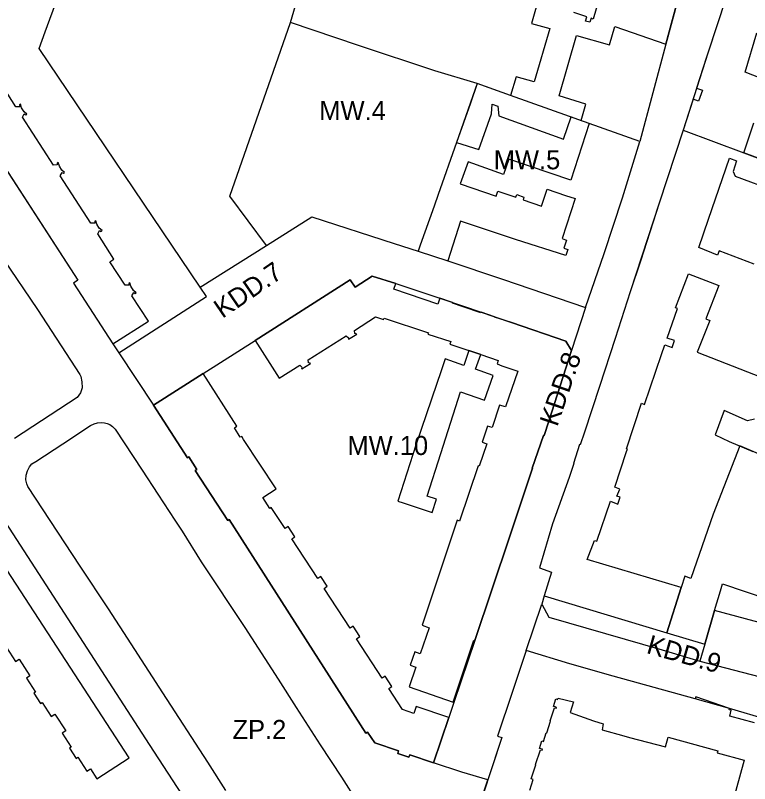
# Model space of a CAD drawing. Extents: x 7424052 to 7425705, y 5546602 to 5547569.
# Drawn here: x 7424972 to 7425164.6, y 5547200.9 to 5547402.5 of the extents above; entities that cross this region are included whole.
import ezdxf

# ---------------------------------------------------------------- set-up
doc = ezdxf.new("R2010")
doc.units = 0
for name, color, linetype in [('linie rozgraniczające', 7, 'Continuous'), ('nieprzekraczalne linie zabudowy', 7, 'Continuous'), ('obowiazujace linie zabudowy', 7, 'Continuous'), ('przeznaczenia terenów', 7, 'Continuous')]:
    doc.layers.add(name, color=color, linetype=linetype)

msp = doc.modelspace()

# ---------------------------------------------------------------- linework, layer by layer
at = {"layer": 'linie rozgraniczające'}
for p, q in [((7424979.78, 5547398.16), (7424986.52, 5547416.78)), ((7425044.17, 5547400.66), (7425048.43, 5547415.4)), ((7425160.51, 5547413.68), (7425153.59, 5547392.63)), ((7425146.34, 5547408.9), (7425142.58, 5547394.99)), ((7425028.21, 5547355.08), (7425044.17, 5547400.66)), ((7425061.96, 5547394.62), (7425044.17, 5547400.66)), ((7424978.19, 5547393.79), (7424979.78, 5547398.16)), ((7425020.45, 5547331.17), (7424978.19, 5547393.79)), ((7425081.99, 5547387.97), (7425061.96, 5547394.62)), ((7425142.58, 5547394.99), (7425135.79, 5547369.42)), ((7425153.59, 5547392.63), (7425147.16, 5547372.35)), ((7425093.12, 5547384.64), (7425081.99, 5547387.97)), ((7425093.12, 5547384.64), (7425087.68, 5547369.12)), ((7425101.87, 5547381.49), (7425093.12, 5547384.64)), ((7425122.45, 5547374.17), (7425101.87, 5547381.49)), ((7424958.41, 5547379.14), (7424988.31, 5547333.01)), ((7425135.79, 5547369.42), (7425122.45, 5547374.17)), ((7425147.16, 5547372.35), (7425140.87, 5547353.27)), ((7425147.16, 5547372.35), (7425163.09, 5547366.42)), ((7425087.68, 5547369.12), (7425082.9, 5547355.52)), ((7425131.26, 5547354.67), (7425135.79, 5547369.42)), ((7425163.09, 5547366.42), (7425169.9, 5547363.89)), ((7425037.82, 5547342.16), (7425028.21, 5547355.08)), ((7425082.9, 5547355.52), (7425081.79, 5547352.43)), ((7425126.4, 5547340.07), (7425131.26, 5547354.67)), ((7425140.87, 5547353.27), (7425133.21, 5547329.93)), ((7425081.79, 5547352.43), (7425078.18, 5547342.21)), ((7425037.82, 5547342.16), (7425049.73, 5547349.69)), ((7425049.73, 5547349.69), (7425071.29, 5547342.69)), ((7425071.29, 5547342.69), (7425077.63, 5547340.63)), ((7425020.45, 5547331.17), (7425037.82, 5547342.16)), ((7425078.18, 5547342.21), (7425077.63, 5547340.63)), ((7425077.63, 5547340.63), (7425085.42, 5547338.09)), ((7425121.54, 5547325.82), (7425126.4, 5547340.07)), ((7424968.75, 5547338.59), (7424977.79, 5547325.37)), ((7425085.42, 5547338.09), (7425099.76, 5547333.31)), ((7424988.31, 5547333.01), (7424987.19, 5547332.23)), ((7425034.89, 5547317.19), (7425059.82, 5547333.16)), ((7425059.82, 5547333.16), (7425061.1, 5547331.18)), ((7425061.1, 5547331.18), (7425065.58, 5547334.1)), ((7425065.58, 5547334.1), (7425071.73, 5547332.17)), ((7425099.76, 5547333.31), (7425121.54, 5547325.82)), ((7424987.19, 5547332.23), (7424997.54, 5547316.35)), ((7425022.12, 5547328.77), (7425020.45, 5547331.17)), ((7425071.73, 5547332.17), (7425083.29, 5547328.28)), ((7424999.07, 5547313.97), (7425022.12, 5547328.77)), ((7425133.21, 5547329.93), (7425129.31, 5547317.69)), ((7425083.29, 5547328.28), (7425089.47, 5547326.17)), ((7424977.79, 5547325.37), (7424988.84, 5547308.24)), ((7425089.47, 5547326.17), (7425102.08, 5547321.92)), ((7425121.54, 5547325.82), (7425117.82, 5547314.6)), ((7425102.08, 5547321.92), (7425116.35, 5547317.03)), ((7425021.23, 5547308.56), (7425034.89, 5547317.19)), ((7425116.35, 5547317.03), (7425117.82, 5547314.6)), ((7425129.31, 5547317.69), (7425125.2, 5547305.13)), ((7424997.54, 5547316.35), (7424999.07, 5547313.97)), ((7425117.82, 5547314.6), (7425111.89, 5547296.03)), ((7424999.07, 5547313.97), (7425008.17, 5547300.22)), ((7425008.17, 5547300.22), (7425021.23, 5547308.56)), ((7424988.84, 5547308.24), (7424989.16, 5547307.73)), ((7424989.16, 5547307.73), (7424989.43, 5547306.38)), ((7424989.43, 5547306.38), (7424989.45, 5547304.76)), ((7424989.45, 5547304.76), (7424989.07, 5547303.47)), ((7425125.2, 5547305.13), (7425121.27, 5547293.17)), ((7424989.07, 5547303.47), (7424988.18, 5547302.22)), ((7424988.18, 5547302.22), (7424971.75, 5547291.5)), ((7425017.07, 5547286.41), (7425008.18, 5547300.23)), ((7424984.37, 5547290.09), (7424991.66, 5547294.88)), ((7424991.66, 5547294.88), (7424992.63, 5547295.38)), ((7424992.63, 5547295.38), (7424993.5, 5547295.63)), ((7424993.5, 5547295.63), (7424994.46, 5547295.72)), ((7424994.46, 5547295.72), (7424995.31, 5547295.64)), ((7424995.31, 5547295.64), (7424996.05, 5547295.45)), ((7424996.05, 5547295.45), (7424996.74, 5547295.14)), ((7424996.74, 5547295.14), (7424997.44, 5547294.66)), ((7424997.44, 5547294.66), (7424998.15, 5547293.93)), ((7425111.89, 5547296.03), (7425110.63, 5547292.24)), ((7424998.15, 5547293.93), (7425005.2, 5547283.18)), ((7425110.49, 5547292.29), (7425107.51, 5547283.73)), ((7425110.63, 5547292.24), (7425110.49, 5547292.29)), ((7425121.27, 5547293.17), (7425120.14, 5547289.84)), ((7424977.35, 5547285.45), (7424984.37, 5547290.09)), ((7425119.96, 5547289.88), (7425118.33, 5547284.94)), ((7425120.14, 5547289.84), (7425119.96, 5547289.88)), ((7425017.46, 5547286.65), (7425017.07, 5547286.41)), ((7425019.58, 5547283.36), (7425017.46, 5547286.65)), ((7424975.67, 5547284.05), (7424976.29, 5547284.82)), ((7424976.29, 5547284.82), (7424977.35, 5547285.45)), ((7425118.47, 5547284.89), (7425117.21, 5547281.22)), ((7425118.33, 5547284.94), (7425118.47, 5547284.89)), ((7424974.79, 5547281.88), (7424975.12, 5547283.03)), ((7424975.12, 5547283.03), (7424975.67, 5547284.05)), ((7425005.2, 5547283.18), (7425009.29, 5547276.93)), ((7425019.11, 5547283.06), (7425019.58, 5547283.36)), ((7425027.65, 5547269.94), (7425019.11, 5547283.06)), ((7425107.65, 5547283.68), (7425106.39, 5547280)), ((7425107.51, 5547283.73), (7425107.65, 5547283.68)), ((7424974.73, 5547280.67), (7424974.79, 5547281.88)), ((7424974.93, 5547279.63), (7424974.73, 5547280.67)), ((7425117.21, 5547281.22), (7425112.87, 5547269.13)), ((7424975.23, 5547278.87), (7424974.93, 5547279.63)), ((7424988.97, 5547258.01), (7424975.23, 5547278.87)), ((7425106.39, 5547280), (7425101.54, 5547265.63)), ((7425009.29, 5547276.93), (7425013.79, 5547270.03)), ((7424967.35, 5547272.4), (7425007.07, 5547211.22)), ((7425028.07, 5547270.21), (7425027.65, 5547269.94)), ((7425063.86, 5547214.15), (7425028.07, 5547270.21)), ((7425013.79, 5547270.03), (7425015.67, 5547267.16)), ((7425112.87, 5547269.13), (7425109.47, 5547257.58)), ((7425015.67, 5547267.16), (7425020.67, 5547259.12)), ((7425101.54, 5547265.63), (7425092.51, 5547238.49)), ((7424996.35, 5547246.79), (7424988.97, 5547258.01)), ((7425020.67, 5547259.12), (7425032.15, 5547241.92)), ((7425109.47, 5547257.58), (7425112.6, 5547256.42)), ((7425112.6, 5547256.42), (7425110.71, 5547250.22)), ((7425110.71, 5547250.22), (7425110.1, 5547248.06)), ((7425105.98, 5547235.9), (7425110.1, 5547248.06)), ((7425110.1, 5547248.06), (7425111.93, 5547244.59)), ((7425002.31, 5547237.66), (7424996.35, 5547246.79)), ((7425111.93, 5547244.59), (7425141.61, 5547236.01)), ((7425032.15, 5547241.92), (7425040.87, 5547228.33)), ((7425092.51, 5547238.49), (7425087.01, 5547222.24)), ((7425010.64, 5547224.75), (7425002.31, 5547237.66)), ((7425105.98, 5547235.9), (7425102.28, 5547224.84)), ((7425117.37, 5547232.36), (7425105.98, 5547235.9)), ((7425141.61, 5547236.01), (7425151.52, 5547233.04)), ((7425128.76, 5547229.1), (7425117.37, 5547232.36)), ((7425151.52, 5547233.04), (7425171.67, 5547227.81)), ((7425040.87, 5547228.33), (7425045.63, 5547220.94)), ((7425146.16, 5547224.31), (7425128.76, 5547229.1)), ((7425022.42, 5547206.57), (7425010.64, 5547224.75)), ((7425102.28, 5547224.84), (7425098.44, 5547213.42)), ((7425150.26, 5547223.17), (7425146.16, 5547224.31)), ((7425087.01, 5547222.24), (7425085.66, 5547218.27)), ((7425150.42, 5547223.71), (7425150.26, 5547223.17)), ((7425159.3, 5547220.65), (7425150.42, 5547223.71)), ((7425045.63, 5547220.94), (7425051.91, 5547211.11)), ((7425169.36, 5547217.69), (7425159.3, 5547220.65)), ((7425085.66, 5547218.27), (7425081.67, 5547206.43)), ((7425064.29, 5547214.41), (7425063.86, 5547214.15)), ((7425066.24, 5547211.66), (7425064.29, 5547214.41)), ((7425072.48, 5547209.54), (7425066.24, 5547211.66)), ((7425099.58, 5547213.04), (7425095.9, 5547201.94)), ((7425098.44, 5547213.42), (7425099.58, 5547213.04)), ((7425007.07, 5547211.22), (7425021.71, 5547188.75)), ((7425051.91, 5547211.11), (7425057.52, 5547202.6)), ((7425072.25, 5547208.86), (7425072.48, 5547209.54)), ((7425075.19, 5547207.88), (7425072.25, 5547208.86)), ((7425075.42, 5547208.54), (7425075.19, 5547207.88)), ((7425081.67, 5547206.43), (7425075.42, 5547208.54)), ((7425027.13, 5547199.15), (7425022.42, 5547206.57)), ((7425089.09, 5547203.92), (7425081.67, 5547206.43)), ((7425095.9, 5547201.94), (7425089.09, 5547203.92)), ((7425057.52, 5547202.6), (7425064.98, 5547191.05)), ((7425089.21, 5547181.77), (7425095.9, 5547201.94))]:
    msp.add_line(p, q, dxfattribs=at)
at = {"layer": 'nieprzekraczalne linie zabudowy'}
for p, q in [((7425037.82, 5547342.16), (7425049.73, 5547349.69)), ((7425049.73, 5547349.69), (7425071.29, 5547342.69)), ((7425071.29, 5547342.69), (7425077.63, 5547340.63)), ((7425090.91, 5547314.54), (7425089.61, 5547310.68)), ((7425094.06, 5547313.54), (7425090.91, 5547314.54)), ((7425092.69, 5547309.66), (7425094.06, 5547313.54)), ((7425084.69, 5547312.39), (7425083.55, 5547309.01)), ((7425089.61, 5547310.68), (7425084.69, 5547312.39)), ((7425083.55, 5547309.01), (7425082.52, 5547305.9)), ((7425097.27, 5547308.03), (7425092.69, 5547309.66)), ((7425095.03, 5547301.55), (7425097.27, 5547308.03)), ((7425082.52, 5547305.9), (7425076.97, 5547289.72)), ((7425083.55, 5547287.55), (7425088.73, 5547303.74)), ((7425088.73, 5547303.74), (7425095.03, 5547301.55)), ((7425076.97, 5547289.72), (7425072.29, 5547275.03)), ((7425161.98, 5547289.55), (7425155.02, 5547271.65)), ((7425169.76, 5547286.23), (7425161.98, 5547289.55)), ((7425079.96, 5547276.32), (7425083.55, 5547287.55)), ((7425082.39, 5547275.55), (7425079.96, 5547276.32)), ((7425072.29, 5547275.03), (7425073.65, 5547274.59)), ((7425073.65, 5547274.59), (7425081.27, 5547272.11)), ((7425081.27, 5547272.11), (7425082.39, 5547275.55)), ((7425155.02, 5547271.65), (7425149.12, 5547254.77)), ((7425147.57, 5547255.41), (7425146.62, 5547252.39)), ((7425149.12, 5547254.77), (7425147.57, 5547255.41)), ((7425146.62, 5547252.39), (7425142.87, 5547240.51)), ((7425156.93, 5547251.53), (7425157.49, 5547253.4)), ((7425157.49, 5547253.4), (7425169.35, 5547249.33)), ((7425155.33, 5547246.36), (7425156.93, 5547251.53)), ((7425152.8, 5547237.51), (7425155.33, 5547246.36)), ((7425142.87, 5547240.51), (7425152.8, 5547237.51))]:
    msp.add_line(p, q, dxfattribs=at)
at = {"layer": 'obowiazujace linie zabudowy'}
for p, q in [((7425021.23, 5547308.56), (7425008.17, 5547300.22)), ((7425030.08, 5547294.73), (7425021.23, 5547308.56)), ((7425008.17, 5547300.22), (7425017.07, 5547286.41)), ((7425029.43, 5547294.25), (7425030.08, 5547294.73)), ((7425030.91, 5547291.87), (7425029.43, 5547294.25)), ((7425031.39, 5547291.98), (7425030.91, 5547291.87)), ((7425031.84, 5547291.27), (7425031.39, 5547291.98)), ((7425031.78, 5547291.22), (7425031.84, 5547291.27)), ((7425040.41, 5547278.3), (7425031.78, 5547291.22)), ((7425017.07, 5547286.41), (7425017.46, 5547286.65)), ((7425017.46, 5547286.65), (7425019.58, 5547283.36)), ((7425019.58, 5547283.36), (7425019.11, 5547283.06)), ((7425019.11, 5547283.06), (7425027.65, 5547269.94)), ((7425036.91, 5547276.02), (7425040.41, 5547278.3)), ((7425038.75, 5547273.17), (7425036.91, 5547276.02)), ((7425036.91, 5547276.02), (7425036.91, 5547276.02)), ((7425039.09, 5547273.4), (7425038.75, 5547273.17)), ((7425042.7, 5547267.86), (7425039.09, 5547273.4)), ((7425027.65, 5547269.94), (7425028.07, 5547270.21)), ((7425028.07, 5547270.21), (7425063.86, 5547214.15)), ((7425043.53, 5547268.39), (7425042.7, 5547267.86)), ((7425045.28, 5547265.71), (7425043.53, 5547268.39)), ((7425044.48, 5547265.2), (7425045.28, 5547265.71)), ((7425051.28, 5547254.77), (7425044.48, 5547265.2)), ((7425052.09, 5547255.3), (7425051.28, 5547254.77)), ((7425053.77, 5547252.72), (7425052.09, 5547255.3)), ((7425052.94, 5547252.17), (7425053.77, 5547252.72)), ((7425059.75, 5547241.72), (7425052.94, 5547252.17)), ((7425155.33, 5547246.36), (7425152.8, 5547237.51)), ((7425175.68, 5547240.94), (7425155.33, 5547246.36)), ((7425060.55, 5547242.24), (7425059.75, 5547241.72)), ((7425062.31, 5547239.55), (7425060.55, 5547242.24)), ((7425061.45, 5547238.95), (7425062.31, 5547239.55)), ((7425068.19, 5547228.62), (7425061.45, 5547238.95)), ((7425152.8, 5547237.51), (7425151.52, 5547233.04)), ((7425151.52, 5547233.04), (7425171.67, 5547227.81)), ((7425068.96, 5547229.12), (7425068.19, 5547228.62)), ((7425070.71, 5547226.44), (7425068.96, 5547229.12)), ((7425069.91, 5547225.92), (7425070.71, 5547226.44)), ((7425073.52, 5547220.38), (7425069.91, 5547225.92)), ((7425076.48, 5547219.31), (7425073.52, 5547220.38)), ((7425077.11, 5547221.16), (7425076.48, 5547219.31)), ((7425085.66, 5547218.27), (7425077.11, 5547221.16)), ((7425081.67, 5547206.43), (7425085.66, 5547218.27)), ((7425063.86, 5547214.15), (7425064.29, 5547214.41)), ((7425064.29, 5547214.41), (7425066.24, 5547211.66)), ((7425066.24, 5547211.66), (7425072.48, 5547209.54)), ((7425072.48, 5547209.54), (7425072.25, 5547208.86)), ((7425072.25, 5547208.86), (7425075.19, 5547207.88)), ((7425075.19, 5547207.88), (7425075.42, 5547208.54)), ((7425075.42, 5547208.54), (7425081.67, 5547206.43))]:
    msp.add_line(p, q, dxfattribs=at)
for points in [[(7425160.51, 5547413.68), (7425153.59, 5547392.63), (7425153.25, 5547391.56), (7425150.67, 5547383.41), (7425152.21, 5547382.86), (7425151.12, 5547379.99), (7425149.75, 5547380.51), (7425147.16, 5547372.35), (7425140.87, 5547353.27), (7425135.9, 5547338.02), (7425133.21, 5547329.93), (7425129.31, 5547317.69), (7425125.2, 5547305.13), (7425121.27, 5547293.17), (7425120.14, 5547289.84), (7425119.96, 5547289.88), (7425118.33, 5547284.94), (7425118.47, 5547284.89), (7425117.21, 5547281.22), (7425112.87, 5547269.13), (7425109.47, 5547257.58), (7425112.6, 5547256.42), (7425110.71, 5547250.22), (7425142.87, 5547240.51), (7425146.62, 5547252.39), (7425121.93, 5547259.77), (7425123.91, 5547264.77), (7425124.48, 5547264.54), (7425128.06, 5547275.06), (7425130.01, 5547274.29), (7425130.63, 5547276.06), (7425129.76, 5547276.39), (7425130.53, 5547278.21), (7425129.23, 5547278.76), (7425132.29, 5547288.05), (7425132.5, 5547288.66), (7425132.27, 5547288.75), (7425136.21, 5547300.74), (7425136.98, 5547300.43), (7425141.43, 5547313.49), (7425142.31, 5547316.07), (7425144.24, 5547315.41), (7425144.84, 5547317.22), (7425142.97, 5547317.84), (7425145.61, 5547325.63), (7425145.08, 5547325.81), (7425148.56, 5547334.73), (7425156.49, 5547331.64), (7425153.07, 5547322.89), (7425154.15, 5547322.44), (7425150.83, 5547314.18), (7425167.56, 5547307.61)], [(7425117.72, 5547375.85), (7425120.37, 5547374.92), (7425121.61, 5547379.18), (7425114.57, 5547381.39), (7425119.17, 5547397.22), (7425127.78, 5547394.76), (7425129.19, 5547399.59), (7425142.58, 5547394.99), (7425146.34, 5547408.9)], [(7425125.26, 5547407.61), (7425123.52, 5547401.54), (7425122.97, 5547401.73), (7425122.63, 5547400.73), (7425121.54, 5547400.99), (7425121.89, 5547402.1), (7425120.78, 5547402.47), (7425118.47, 5547403.26)], [(7425108.75, 5547405.23), (7425107.33, 5547400.34), (7425112.15, 5547399.02), (7425108.08, 5547385.05), (7425103.29, 5547386.37), (7425101.87, 5547381.49), (7425096.21, 5547383.53), (7425093.12, 5547384.64), (7425091.31, 5547379.48), (7425087.68, 5547369.12), (7425093.52, 5547367.29), (7425096.83, 5547376.63), (7425097, 5547379.23), (7425098.54, 5547378.66), (7425098.78, 5547376.16), (7425115.71, 5547370.03), (7425117.72, 5547375.85)], [(7425167.38, 5547386.04), (7425163.36, 5547387.61), (7425166.42, 5547397.9)], [(7424958.41, 5547379.14), (7424988.31, 5547333.01), (7424987.19, 5547332.23), (7424997.54, 5547316.35), (7425006.88, 5547322.26), (7425002.55, 5547328.93), (7425003.01, 5547329.77), (7425003.42, 5547329.55), (7425003.67, 5547329.74), (7425002.93, 5547330.36), (7425002.24, 5547331.43), (7425001.99, 5547332.36), (7425001.73, 5547332.2), (7425001.77, 5547331.75), (7425000.76, 5547331.68), (7424996.73, 5547337.87), (7424997.83, 5547338.57), (7424993.56, 5547345.2), (7424994.05, 5547346.08), (7424994.46, 5547345.84), (7424994.71, 5547346.03), (7424993.98, 5547346.65), (7424993.3, 5547347.72), (7424993.04, 5547348.64), (7424992.79, 5547348.48), (7424992.81, 5547348.01), (7424991.79, 5547347.95), (7424983.74, 5547360.44), (7424984.22, 5547361.32), (7424984.62, 5547361.11), (7424984.87, 5547361.27), (7424984.14, 5547361.89), (7424983.57, 5547362.98), (7424983.18, 5547363.89), (7424982.94, 5547363.75), (7424982.96, 5547363.28), (7424981.98, 5547363.18), (7424973.85, 5547375.79), (7424974.31, 5547376.64), (7424974.73, 5547376.41), (7424975.01, 5547376.58), (7424974.26, 5547377.21), (7424973.55, 5547378.27), (7424973.31, 5547379.21), (7424973.07, 5547379.05), (7424973.09, 5547378.53), (7424972.11, 5547378.49), (7424967.81, 5547385.17)], [(7425117.67, 5547359.3), (7425101.41, 5547364.82), (7425100.03, 5547360.79), (7425090.7, 5547364.1), (7425088.63, 5547358.29), (7425098.07, 5547355.06), (7425098.53, 5547356.4), (7425103.28, 5547354.77), (7425103.53, 5547355.48), (7425105.37, 5547354.85), (7425105.13, 5547354.14), (7425110, 5547352.48), (7425111.5, 5547356.91), (7425116.31, 5547355.28), (7425118.79, 5547354.44), (7425115.39, 5547343.94), (7425116.23, 5547343.65), (7425116.54, 5547343.54), (7425115.79, 5547341.39), (7425116.91, 5547341.12), (7425116.38, 5547339.53), (7425103.16, 5547343.73), (7425088.72, 5547348.55), (7425085.42, 5547338.09), (7425099.76, 5547333.31), (7425121.54, 5547325.82), (7425126.4, 5547340.07), (7425131.26, 5547354.67), (7425135.79, 5547369.42), (7425122.45, 5547374.17), (7425117.67, 5547359.3)], [(7425169.9, 5547363.89), (7425163.09, 5547366.42), (7425165.65, 5547374.29)], [(7425165.76, 5547337.2), (7425156.6, 5547340.77), (7425156.15, 5547339.63), (7425151.21, 5547341.56), (7425153.75, 5547349.03), (7425159.27, 5547365.02), (7425161.13, 5547364.31), (7425160.21, 5547361.51), (7425160.76, 5547360.35), (7425171.22, 5547356.51)], [(7425094.06, 5547313.54), (7425098.63, 5547311.94), (7425098.32, 5547311.07), (7425099.58, 5547310.6), (7425103.72, 5547309.2), (7425100.49, 5547299.76), (7425098.96, 5547300.26), (7425097.02, 5547294.35), (7425095.79, 5547294.7), (7425094.39, 5547290.51), (7425095.63, 5547290.1), (7425093.62, 5547284.22), (7425093.34, 5547284.31), (7425088.45, 5547269.84), (7425087.84, 5547270.04), (7425078.67, 5547242.51), (7425080.54, 5547241.86), (7425078.15, 5547235), (7425076.75, 5547235.51), (7425075.53, 5547232.04), (7425077.01, 5547231.5), (7425075.29, 5547226.31), (7425086.8, 5547222.31), (7425092.24, 5547238.57), (7425092.51, 5547238.49), (7425101.54, 5547265.63), (7425106.39, 5547280), (7425107.65, 5547283.68), (7425107.51, 5547283.73), (7425110.49, 5547292.29), (7425110.63, 5547292.24), (7425111.89, 5547296.03), (7425117.82, 5547314.6), (7425116.35, 5547317.03), (7425102.08, 5547321.92), (7425097.6, 5547323.36), (7425097.62, 5547323.42), (7425094.14, 5547324.6), (7425094.09, 5547324.5), (7425089.42, 5547326.03), (7425086.59, 5547327.03), (7425086.63, 5547327.14), (7425086.38, 5547327.22), (7425083.29, 5547328.28), (7425082.77, 5547326.76), (7425071.2, 5547330.65), (7425071.73, 5547332.17), (7425065.58, 5547334.1), (7425061.1, 5547331.18), (7425059.82, 5547333.16), (7425034.89, 5547317.19), (7425041.2, 5547307.28), (7425046.58, 5547310.69), (7425047.14, 5547310.2), (7425047, 5547310.03), (7425047.14, 5547309.8), (7425049.34, 5547311.19), (7425049.29, 5547311.26), (7425048.84, 5547311.3), (7425048.77, 5547312.09), (7425058.76, 5547318.44), (7425059.36, 5547317.9), (7425059.35, 5547317.51), (7425061.49, 5547318.89), (7425060.99, 5547319.05), (7425060.91, 5547319.8), (7425066.45, 5547323.41), (7425068.56, 5547322.75), (7425068.67, 5547323.07), (7425080.3, 5547319.19), (7425080.16, 5547318.86), (7425086.2, 5547316.9), (7425085.96, 5547316.2), (7425090.92, 5547314.57), (7425094.06, 5547313.54)], [(7425165.81, 5547296.53), (7425164.05, 5547296.15), (7425157.85, 5547298.81), (7425155.56, 5547292.45), (7425159.24, 5547290.72), (7425163.14, 5547289.06), (7425165.41, 5547288.09)], [(7424969.6, 5547236.67), (7424972.01, 5547232.96), (7424972.93, 5547233.63), (7424975.79, 5547229.22), (7424974.85, 5547228.6), (7424977.24, 5547224.94), (7424976.8, 5547224.65), (7424978.56, 5547221.98), (7424978.99, 5547222.25), (7424981.37, 5547218.59), (7424982.32, 5547219.21), (7424985.16, 5547214.79), (7424984.25, 5547214.18), (7424986.63, 5547210.53), (7424986.2, 5547210.24), (7424987.93, 5547207.55), (7424988.38, 5547207.85), (7424990.74, 5547204.22), (7424991.64, 5547204.82), (7424993.33, 5547202.24), (7425001.78, 5547207.7), (7424963.81, 5547266.06)], [(7425165.85, 5547216.87), (7425159.35, 5547218.66), (7425159.76, 5547220.19), (7425159.21, 5547220.34), (7425159.3, 5547220.65), (7425150.26, 5547223.17), (7425146.16, 5547224.31), (7425128.76, 5547229.1), (7425117.37, 5547232.36), (7425105.98, 5547235.9), (7425102.28, 5547224.84), (7425098.44, 5547213.42), (7425099.58, 5547213.04), (7425089.21, 5547181.77)], [(7425106.9, 5547199.27), (7425107.81, 5547202), (7425107.3, 5547202.17), (7425108.52, 5547205.9), (7425108.44, 5547205.92), (7425109.73, 5547209.79), (7425110.13, 5547209.68), (7425110.22, 5547209.96), (7425109.44, 5547210.13), (7425110.07, 5547212.14), (7425110.49, 5547211.99), (7425111.23, 5547214.26), (7425111.37, 5547214.23), (7425112.37, 5547217.37), (7425112.27, 5547217.44), (7425113.39, 5547220.84), (7425113.85, 5547220.72), (7425113.89, 5547220.82), (7425113.92, 5547220.91), (7425113.52, 5547221.05), (7425113.08, 5547221.2), (7425113.72, 5547223.15), (7425114.2, 5547223.03), (7425114.32, 5547223.4)], [(7425114.32, 5547223.4), (7425118.4, 5547222.43), (7425117.45, 5547219.63), (7425123.63, 5547217.39), (7425126.13, 5547216.6), (7425125.89, 5547215.03), (7425131.54, 5547213.46), (7425133.04, 5547213.04), (7425142.47, 5547210.57), (7425143.16, 5547213.14), (7425156.22, 5547209.54), (7425156.08, 5547209.04), (7425163.15, 5547207.08), (7425157.81, 5547187.71), (7425173.37, 5547183.41)]]:
    msp.add_lwpolyline(points, dxfattribs=at)

# ---------------------------------------------------------------- texts
at = {"layer": 'przeznaczenia terenów'}
for s, p in [('MW.4', (7425051.68, 5547375.01)), ('MW.5', (7425097.44, 5547362.12)), ('MW.10', (7425059.06, 5547287.16)), ('ZP.2', (7425028.91, 5547212.65))]:
    msp.add_text(s, height=5, dxfattribs=at).set_placement(p)
for s, rotation, p in [('KDD.7', 34.4371, (7425026.25, 5547322.86)), ('KDD.8', 71.1329, (7425114.1, 5547294.4)), ('KDD.9', 344.106, (7425137.26, 5547235.25))]:
    msp.add_text(s, height=5, rotation=rotation, dxfattribs=at).set_placement(p)

doc.saveas('drawing.dxf')
